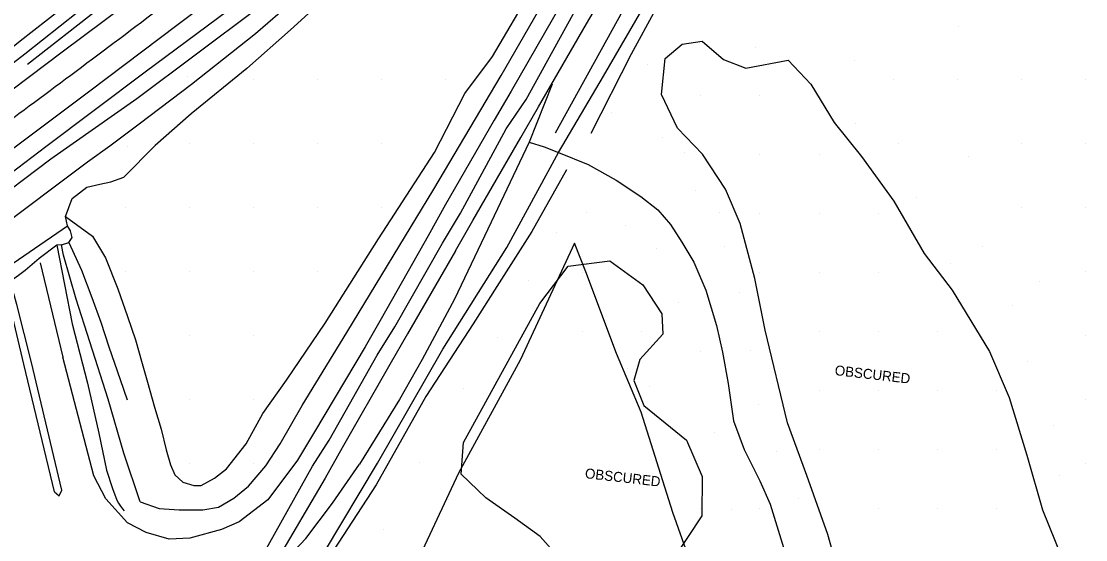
# Model space of a CAD drawing. Extents: x 524772 to 528246, y 273285 to 283088.
# Drawn here: x 526864.4 to 527026.6, y 277303.2 to 277382.3 of the extents above; entities that cross this region are included whole.
import ezdxf

# ---------------------------------------------------------------- set-up
doc = ezdxf.new("R2010")
doc.units = 0
for name, color, linetype in [('Exist DTM Crownline', 7, 'Continuous'), ('Exist DTM Spot Elevation CELL', 7, 'Continuous'), ('Exist Roads EOP', 7, 'Continuous'), ('Old_Level_12', 7, 'Continuous'), ('PH Exist DTM Breakline', 7, 'Continuous'), ('PH Exist DTM Obscure Area', 7, 'Continuous'), ('PH Exist DTM Obscure Area Text', 7, 'Continuous'), ('PH Exist DTM Point', 7, 'Continuous')]:
    doc.layers.add(name, color=color, linetype=linetype)

msp = doc.modelspace()

# ---------------------------------------------------------------- linework, layer by layer
at = {"layer": 'Exist DTM Crownline'}
for points in [[(526928.61, 277348.41), (526931.35, 277353), (526938.32, 277365.86), (526941.36, 277370.32), (526948.55, 277383.35), (526951.36, 277387.64), (526958.38, 277400.18)], [(526901.35, 277301.04), (526908.81, 277314.4), (526911.35, 277318.36), (526918.66, 277331.36), (526921.35, 277335.68), (526928.61, 277348.41)]]:
    msp.add_lwpolyline(points, dxfattribs=at)
msp.add_spline([(527011.17, 277478.06), (526999.87, 277470.1), (526987.44, 277460.96), (526975.06, 277451.74), (526962.63, 277442.45), (526949.98, 277432.96), (526937.25, 277423.35), (526923.93, 277413.31), (526911.47, 277403.88), (526898.66, 277394.17), (526886.05, 277384.62), (526872.77, 277374.62), (526860.1, 277365.18), (526847.11, 277355.34)], degree=3, dxfattribs=at)
at = {"layer": 'Exist DTM Spot Elevation CELL'}
msp.add_line((526956.79, 277329.24), (526956.79, 277329.24), dxfattribs=at)
at = {"layer": 'Exist Roads EOP'}
for points in [[(527002.14, 277467.05), (526990.29, 277458.43), (526977.96, 277449.39), (526964.96, 277439.62), (526952.28, 277430.11), (526939.19, 277420.22), (526927.11, 277411.11), (526913.98, 277401.22), (526900.84, 277391.21), (526888.12, 277381.63), (526874.88, 277371.64), (526862.48, 277362.33), (526849.34, 277352.38)], [(526844.8, 277358.15), (526857.97, 277368.04), (526870.67, 277377.62), (526883.64, 277387.37), (526896.44, 277397.03), (526909.42, 277406.87), (526922.35, 277416.65), (526935.05, 277426.24), (526947.88, 277435.92), (526960.62, 277445.47), (526973.4, 277455.12), (526973.69, 277455.3)], [(526956.47, 277401.5), (526949.1, 277388.94), (526946.71, 277384.91), (526939.1, 277371.62), (526936.5, 277367.19), (526929.1, 277354.3), (526926.43, 277349.54)], [(526930.59, 277347.23), (526933.26, 277351.9), (526940.57, 277364.56), (526943.26, 277369.22), (526950.56, 277381.87), (526953.26, 277386.54), (526960.63, 277399.04)], [(526926.43, 277349.54), (526919.28, 277336.88), (526916.81, 277332.59), (526909.1, 277319.66), (526906.52, 277315.33), (526902.01, 277309.28), (526897.64, 277305.93), (526894.94, 277304.74), (526890.11, 277303.39)], [(526930.59, 277347.23), (526923.26, 277334.58), (526920.61, 277329.93), (526913.35, 277317.21), (526910.72, 277312.56), (526903.28, 277299.87)], [(526867.3, 277345.42), (526870.78, 277331.04)], [(526865.96, 277330.21), (526863.76, 277339.05), (526863.3, 277340.67), (526862.89, 277341.87)], [(526864.83, 277329.94), (526862.47, 277339.86), (526861.93, 277341.39)], [(526890.11, 277303.39), (526886.96, 277303.28), (526883.48, 277304.3), (526880.59, 277305.74), (526877.29, 277309.39), (526875.49, 277312.95), (526870.78, 277331.04)], [(526869.47, 277310.48), (526864.83, 277329.94)], [(526870.59, 277310.75), (526865.96, 277330.21)], [(526869.47, 277310.47), (526870.2, 277309.88), (526870.59, 277310.73)]]:
    msp.add_lwpolyline(points, dxfattribs=at)
at = {"layer": 'Old_Level_12'}
msp.add_lwpolyline([(526968.01, 277295.26), (526963.74, 277307.32), (526958.88, 277322.62), (526955.12, 277331.57), (526950.46, 277344.07), (526948.73, 277348.44), (526940.44, 277330.59), (526931.08, 277313.31), (526923.72, 277297.66)], dxfattribs=at)
at = {"layer": 'PH Exist DTM Breakline'}
for points in [[(526845.18, 277363.98), (526864.26, 277379.28), (526870.49, 277384.16), (526884.16, 277394.51), (526899.98, 277406.05), (526912.48, 277415.71), (526930.2, 277429.24), (526942.85, 277438.76), (526954.42, 277448.17), (526957.59, 277450.76), (526958.75, 277451.28), (526959.2, 277451.49), (526961.14, 277452.94), (526963.73, 277455.07), (526968.45, 277458.83), (526978.78, 277466.21), (526987.6, 277472.82), (526992.45, 277476.75), (526997.11, 277479.95), (527001.01, 277482.26), (527005.21, 277484.66)], [(526993.89, 277475.7), (526979.73, 277463.41), (526972.73, 277457.55), (526962.38, 277449.35), (526948.03, 277438.46), (526928.18, 277423.69), (526900.38, 277402.78), (526876.31, 277384.23), (526865.35, 277375.69)], [(526976.02, 277462.36), (526965.59, 277454.45), (526961.52, 277450.82), (526957.09, 277447.48), (526952.83, 277444.33), (526949.19, 277441.56), (526936.05, 277432.12), (526922.6, 277421.83), (526901.9, 277405.95), (526883.79, 277392.25), (526864.96, 277377.26), (526845.57, 277362.3)], [(526847.82, 277347.7), (526868.14, 277363.19), (526883.29, 277374.56), (526905.35, 277390.98), (526933.45, 277412.19), (526950.67, 277425.04), (526965.88, 277436.15), (526983.48, 277449.89), (526995.5, 277459.84)], [(526951.26, 277365.19), (526957.42, 277377.32), (526961.14, 277384.11), (526963.71, 277388.74), (526967.36, 277394.88), (526970.07, 277398.91), (526973.47, 277403.31), (526976.54, 277407.26), (526979.75, 277412.17), (526982.98, 277416.19), (526993.46, 277427.78), (526999.3, 277433.54), (527009.91, 277443.87)], [(526976.94, 277439.76), (526969.93, 277433.96), (526964.24, 277429.65), (526954.42, 277422.4), (526944.07, 277414.62), (526936.46, 277408.84), (526929.57, 277404.02), (526924.19, 277399.21), (526917.68, 277392.52), (526912.12, 277387.09), (526905.47, 277380.98), (526898.82, 277375.07), (526890.33, 277368.18), (526884.81, 277363.33), (526880.05, 277358.48)], [(526849.2, 277341.8), (526869.42, 277357.02), (526874.51, 277360.85), (526877.93, 277363.28), (526882.38, 277366.62), (526890.38, 277372.7), (526900.11, 277380.44), (526909.54, 277388.58), (526919.68, 277397.33)], [(526882.54, 277308.94), (526885.46, 277307.93), (526888.49, 277307.72), (526892.1, 277307.74), (526894.46, 277308.15), (526896.83, 277309.52), (526899.05, 277311.33), (526901.68, 277314.44), (526903.9, 277317.82), (526907.23, 277323.66), (526914.04, 277334.8), (526927.3, 277356.67), (526937.58, 277374.01), (526946.87, 277390.18)], [(526959.55, 277390.22), (526945.78, 277365.23)], [(526871.15, 277352.47), (526875.29, 277349.47), (526877.26, 277346.19), (526879.13, 277341.45), (526880.59, 277337.25), (526881.85, 277333.69), (526882.87, 277330.08), (526883.68, 277327.22), (526884.75, 277323.42), (526885.74, 277320.02), (526886.51, 277316.88), (526887.19, 277314.61), (526887.82, 277313.06), (526889.04, 277311.95), (526890.7, 277311.44), (526891.84, 277311.44), (526893.89, 277312.55), (526895.72, 277314.01), (526898.69, 277317.83), (526901.23, 277322.42), (526904.83, 277327.53), (526910.75, 277336.22), (526918.85, 277349.11), (526927.38, 277362.24), (526932, 277371.26), (526936.22, 277376.91), (526942.31, 277387.25)], [(526900.23, 277384.1), (526882.04, 277370.44), (526868.94, 277361.26), (526848.44, 277345.76)], [(526910.63, 277301.33), (526918.69, 277314.88), (526928.65, 277332.26), (526938.43, 277347.75), (526946.29, 277362.25), (526953.16, 277373.9), (526959.89, 277385.6)], [(526945.34, 277372.66), (526941.83, 277363.81), (526935.51, 277350.57), (526930.46, 277339.89), (526925.54, 277330.66), (526922.08, 277324.57), (526915.99, 277314.68)], [(526941.83, 277363.81), (526944.12, 277363.13), (526946.29, 277362.25)], [(526946.29, 277362.25), (526950.84, 277360.41), (526955.09, 277358.05), (526958.86, 277355.55), (526961.44, 277353.53), (526963.39, 277351.25), (526965.1, 277348.6), (526966.91, 277345.51), (526968.75, 277341.23), (526970.4, 277335.87), (526971.3, 277331.81), (526972.17, 277327.02), (526972.95, 277321.32), (526974.62, 277316.93), (526976.98, 277312.16), (526978.57, 277308.62), (526980.57, 277301.99)], [(526870.57, 277348.17), (526871.68, 277348.55), (526872.16, 277349.31), (526871.9, 277350.29), (526871.48, 277351.09), (526871.15, 277352.47), (526872.19, 277355.22), (526874.4, 277356.95), (526876.37, 277357.45), (526878.07, 277357.79), (526880.05, 277358.48)], [(526947.52, 277359.6), (526942.24, 277350.19), (526936.91, 277341.79), (526933.3, 277336.13), (526926.06, 277325.05), (526918.5, 277311.57), (526911.32, 277300.46)], [(526850.49, 277336.67), (526871.48, 277351.09)], [(526871.68, 277348.55), (526873.61, 277344.32), (526875.2, 277340.12), (526876.53, 277336.36), (526877.78, 277332.62), (526879.5, 277327.64), (526880.56, 277324.52)], [(526882.54, 277308.94), (526880.04, 277316.4), (526877.66, 277324.62), (526874.88, 277333.38), (526872.81, 277339.86), (526870.87, 277346.6), (526870.57, 277348.17), (526869.85, 277348.13), (526867.14, 277346.09), (526865, 277344.25), (526862.65, 277342.47), (526861.48, 277341.67), (526858.38, 277339.4), (526854.6, 277336.62)], [(526869.85, 277348.13), (526872.2, 277336.1)], [(526872.2, 277336.1), (526874.54, 277327.08), (526876.22, 277319.44), (526877.39, 277313.78), (526878.31, 277311.01), (526878.99, 277309.2), (526879.26, 277308.75), (526879.55, 277308.31), (526879.85, 277307.89), (526880.1, 277307.57)], [(526901.89, 277297.09), (526907.8, 277303.37), (526911.83, 277308.77), (526915.99, 277314.68)]]:
    msp.add_lwpolyline(points, dxfattribs=at)
at = {"layer": 'PH Exist DTM Obscure Area'}
for points in [[(526989.99, 277294.55), (526987.34, 277303.98), (526984.13, 277312.98), (526981.18, 277320.99), (526977.8, 277335.15), (526976.24, 277343.03), (526973.96, 277351.45), (526971.77, 277356.65), (526968.25, 277362.02), (526964.42, 277365.97), (526961.99, 277371.09), (526962.55, 277376.6), (526965.16, 277378.8), (526968.2, 277379.24), (526971.45, 277376.44), (526974.83, 277375.15), (526981.31, 277376.33), (526984.78, 277372.71), (526988.29, 277366.83), (526992.46, 277361.65), (526997.38, 277354.85), (527002.02, 277346.85), (527006.31, 277341.26), (527012.01, 277331.88), (527014.98, 277324.88), (527017.66, 277316.07), (527020.06, 277307.74), (527023.8, 277298.44)], [(526947.89, 277298.74), (526943.51, 277303.67), (526939.65, 277306.49), (526935.21, 277309.56), (526931.45, 277313.16), (526931.81, 277318.02), (526943.46, 277339.22), (526947.77, 277344.92), (526954.14, 277345.72), (526959.13, 277342.07), (526962.04, 277337.62), (526962.2, 277334.55), (526958.7, 277330.67), (526957.77, 277327.46), (526959.3, 277323.65), (526965.82, 277318.39), (526968.2, 277312.83), (526968.13, 277306.8), (526963.9, 277300.36)]]:
    msp.add_lwpolyline(points, dxfattribs=at)
at = {"layer": 'PH Exist DTM Point'}
for p, q in [((527007.28, 277381.49), (527007.28, 277381.49)), ((526976.25, 277378.32), (526976.25, 277378.32)), ((526991.4, 277376.22), (526991.4, 277376.22)), ((526959.93, 277375.61), (526959.93, 277375.61)), ((526889.79, 277373.8), (526889.79, 277373.8)), ((526899.84, 277373.37), (526899.84, 277373.37)), ((526909.58, 277373.35), (526909.58, 277373.35)), ((526919.35, 277373.37), (526919.35, 277373.37)), ((526929.1, 277373.37), (526929.1, 277373.37)), ((526997.38, 277373.37), (526997.38, 277373.37)), ((527007.13, 277373.37), (527007.13, 277373.37)), ((527016.88, 277373.37), (527016.88, 277373.37)), ((527026.64, 277373.37), (527026.64, 277373.37)), ((526968, 277371), (526968, 277371)), ((526977, 277371), (526977, 277371)), ((526954.42, 277368.37), (526954.42, 277368.37)), ((526991.5, 277366.64), (526991.5, 277366.64)), ((526880.63, 277363.11), (526880.63, 277363.11)), ((526890.09, 277363.61), (526890.09, 277363.61)), ((526899.82, 277363.6), (526899.82, 277363.6)), ((526909.59, 277363.61), (526909.59, 277363.61)), ((526919.35, 277363.61), (526919.35, 277363.61)), ((526962.1, 277364.56), (526962.1, 277364.56)), ((526998.16, 277363.61), (526998.16, 277363.61)), ((527016.88, 277363.58), (527016.88, 277363.58)), ((527026.62, 277363.63), (527026.62, 277363.63)), ((526965.51, 277362.2), (526965.51, 277362.2)), ((526977, 277362), (526977, 277362)), ((526986, 277362), (526986, 277362)), ((527008.73, 277361.62), (527008.73, 277361.62)), ((526967.11, 277356.51), (526967.11, 277356.51)), ((527000.93, 277355.43), (527000.93, 277355.43)), ((526880.32, 277353.87), (526880.32, 277353.87)), ((526890.09, 277353.86), (526890.09, 277353.86)), ((526899.86, 277353.87), (526899.86, 277353.87)), ((526909.59, 277353.86), (526909.59, 277353.86)), ((526919.36, 277353.87), (526919.36, 277353.87)), ((527016.89, 277353.89), (527016.89, 277353.89)), ((527026.65, 277353.84), (527026.65, 277353.84)), ((526950.62, 277353.13), (526950.62, 277353.13)), ((526970.76, 277353.15), (526970.76, 277353.15)), ((526977, 277353), (526977, 277353)), ((526986, 277353), (526986, 277353)), ((526995, 277353), (526995, 277353)), ((526945.93, 277350.03), (526945.93, 277350.03)), ((526956.58, 277351.05), (526956.58, 277351.05)), ((526961.3, 277347.56), (526961.3, 277347.56)), ((526971.67, 277347.84), (526971.67, 277347.84)), ((527010.86, 277347.87), (527010.86, 277347.87)), ((527006.11, 277345.3), (527006.11, 277345.3)), ((526880.33, 277344.1), (526880.33, 277344.1)), ((526890.09, 277344.1), (526890.09, 277344.1)), ((526899.84, 277344.1), (526899.84, 277344.1)), ((526909.59, 277344.1), (526909.59, 277344.1)), ((526950, 277344), (526950, 277344)), ((526977, 277344), (526977, 277344)), ((526986, 277344), (526986, 277344)), ((526995, 277344), (526995, 277344)), ((527026.64, 277344.1), (527026.64, 277344.1)), ((526941.72, 277342.68), (526941.72, 277342.68)), ((527019.66, 277342.52), (527019.66, 277342.52)), ((526973.92, 277340.88), (526973.92, 277340.88)), ((526964.64, 277339.31), (526964.64, 277339.31)), ((527015.47, 277338.88), (527015.47, 277338.88)), ((526890.09, 277334.35), (526890.09, 277334.35)), ((526899.84, 277334.35), (526899.84, 277334.35)), ((526936.96, 277333.99), (526936.96, 277333.99)), ((526941.04, 277334.96), (526941.04, 277334.96)), ((526950, 277335), (526950, 277335)), ((526959, 277335), (526959, 277335)), ((526986, 277335), (526986, 277335)), ((526995, 277335), (526995, 277335)), ((527004, 277335), (527004, 277335)), ((527026.64, 277334.35), (527026.64, 277334.35)), ((526967.92, 277331.94), (526967.92, 277331.94)), ((526975.49, 277332.03), (526975.49, 277332.03)), ((527017.85, 277330.37), (527017.85, 277330.37)), ((526931.78, 277326.32), (526931.78, 277326.32)), ((526960.2, 277326.55), (526960.2, 277326.55)), ((526986, 277326), (526986, 277326)), ((526995, 277326), (526995, 277326)), ((527004, 277326), (527004, 277326)), ((527013, 277326), (527013, 277326)), ((526890.09, 277324.6), (526890.09, 277324.6)), ((526899.84, 277324.6), (526899.84, 277324.6)), ((527026.64, 277324.6), (527026.64, 277324.6)), ((526976.8, 277323.84), (526976.8, 277323.84)), ((526970.1, 277319.5), (526970.1, 277319.5)), ((527021.69, 277320.58), (527021.69, 277320.58)), ((526979.46, 277316.69), (526979.46, 277316.69)), ((526986, 277317), (526986, 277317)), ((526995.01, 277316.99), (526995.01, 277316.99)), ((527004, 277316.98), (527004, 277316.98)), ((527013, 277317), (527013, 277317)), ((526890.09, 277314.84), (526890.09, 277314.84)), ((526899.84, 277314.84), (526899.84, 277314.84)), ((526925.15, 277314.96), (526925.15, 277314.96)), ((527026.64, 277314.84), (527026.64, 277314.84)), ((527022.66, 277312.9), (527022.66, 277312.9)), ((526929.46, 277309.34), (526929.46, 277309.34)), ((526968, 277308), (526968, 277308)), ((526972.63, 277307.86), (526972.63, 277307.86)), ((526977, 277308), (526977, 277308)), ((526982.95, 277309.4), (526982.95, 277309.4)), ((526995, 277308), (526995, 277308)), ((527004, 277307.99), (527004, 277307.99)), ((527013, 277308), (527013, 277308)), ((526919.7, 277304.73), (526919.7, 277304.73))]:
    msp.add_line(p, q, dxfattribs=at)

# ---------------------------------------------------------------- texts
at = {"layer": 'PH Exist DTM Obscure Area Text'}
for p in [(526988.34, 277328.3), (526950.27, 277312.58)]:
    msp.add_text('OBSCURED', height=1.524, rotation=353.4693, dxfattribs=at).set_placement(p)

doc.saveas('drawing.dxf')
